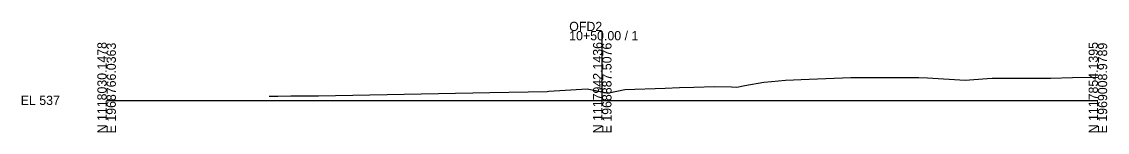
# Model space of a CAD drawing. Extents: x 9974 to 10303, y 9990 to 12021.
# Drawn here: x 9974.3 to 10302.8, y 10490.3 to 10523.9 of the extents above; entities that cross this region are included whole.
import ezdxf

# ---------------------------------------------------------------- set-up
doc = ezdxf.new("R2010")
doc.units = 0
for name, color, linetype in [('Level 10', 7, 'Continuous'), ('Level 60', 7, 'Continuous'), ('Level 63', 7, 'Continuous')]:
    doc.layers.add(name, color=color, linetype=linetype)

msp = doc.modelspace()

# ---------------------------------------------------------------- linework, layer by layer
at = {"layer": 'Level 60'}
for p, q in [((10212.57, 10506.45), (10225.25, 10506.97)), ((10225.25, 10506.97), (10230.97, 10506.96)), ((10230.97, 10506.96), (10240.18, 10506.97)), ((10240.18, 10506.97), (10242.87, 10506.96)), ((10242.87, 10506.96), (10245.77, 10506.95)), ((10245.77, 10506.95), (10248.39, 10506.79)), ((10248.39, 10506.79), (10259.86, 10506.08)), ((10259.86, 10506.08), (10266.52, 10506.59)), ((10266.52, 10506.59), (10267.97, 10506.71)), ((10267.97, 10506.71), (10271.08, 10506.71)), ((10271.08, 10506.71), (10285.75, 10506.72)), ((10285.75, 10506.72), (10292.35, 10506.94)), ((10292.35, 10506.94), (10300, 10507.01)), ((10133.83, 10502.76), (10145.46, 10503.47)), ((10145.46, 10503.47), (10150, 10502.58)), ((10152.03, 10502.27), (10156.81, 10503.31)), ((10156.81, 10503.31), (10169.03, 10503.72)), ((10169.03, 10503.72), (10173.42, 10503.9)), ((10173.42, 10503.9), (10177.71, 10504.03)), ((10177.71, 10504.03), (10184.04, 10504.22)), ((10184.04, 10504.22), (10189.09, 10504.11)), ((10189.09, 10504.11), (10190.72, 10504.04)), ((10190.72, 10504.04), (10193.12, 10504.47)), ((10193.12, 10504.47), (10198.89, 10505.49)), ((10198.89, 10505.49), (10201.2, 10505.72)), ((10201.2, 10505.72), (10205.5, 10506.17)), ((10205.5, 10506.17), (10212.57, 10506.45)), ((10049.16, 10501.25), (10051.85, 10501.25)), ((10051.85, 10501.25), (10055.75, 10501.34)), ((10055.75, 10501.34), (10064.14, 10501.33)), ((10064.14, 10501.33), (10115.94, 10502.36)), ((10115.94, 10502.36), (10133.3, 10502.74)), ((10133.3, 10502.74), (10133.83, 10502.76)), ((10150, 10502.58), (10151.69, 10502.22)), ((10151.69, 10502.22), (10152.03, 10502.27))]:
    msp.add_line(p, q, dxfattribs=at)
at = {"layer": 'Level 63'}
for p, q in [((10150, 10500), (10150, 10521.02)), ((10000, 10500), (10150, 10500)), ((10150, 10500), (10300, 10500))]:
    msp.add_line(p, q, dxfattribs=at)

# ---------------------------------------------------------------- texts
at = {"layer": 'Level 10'}
msp.add_text('539.578', height=0.8, rotation=90, dxfattribs=at).set_placement((10149.9, 10503.08))
at = {"layer": 'Level 63'}
for s, p in [('OFD2', (10140, 10521.02)), ('10+50.00 / 1', (10140, 10518.22)), ('EL 537', (9974, 10498.6))]:
    msp.add_text(s, height=2.8, dxfattribs=at).set_placement(p)
for s, p in [('N 1118030.1478', (10000, 10490)), ('E 1968766.0363', (10002.8, 10490)), ('N 1117942.1436', (10150, 10490)), ('E 1968887.5076', (10152.8, 10490)), ('N 1117854.1395', (10300, 10490)), ('E 1969008.9789', (10302.8, 10490))]:
    msp.add_text(s, height=2.8, rotation=90, dxfattribs=at).set_placement(p)

doc.saveas('drawing.dxf')
